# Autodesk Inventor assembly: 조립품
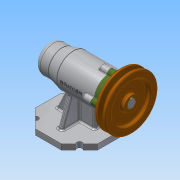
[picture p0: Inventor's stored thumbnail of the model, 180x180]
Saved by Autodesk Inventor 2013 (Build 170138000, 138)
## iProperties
Created: 2019-12
Part Number: 조립품
Document SubType Name: Assembly
Designer: Administrator
Author: Administrator
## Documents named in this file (12)
- C:\Users\Administrator\Desktop\491204V1027\조립품.iam
- C:\Users\Administrator\Desktop\491204V1027\본체.ipt
- C:\Users\Administrator\Desktop\491204V1027\축.ipt
- C:\Users\Administrator\Desktop\491204V1027\커버.ipt
- C:\Users\Administrator\Desktop\491204V1027\베어링 6004.ipt
- C:\Users\Administrator\Desktop\491204V1027\어댑터슬리브.ipt
- C:\Users\Administrator\Desktop\491204V1027\베어링 51202.ipt
- C:\Users\Administrator\Desktop\491204V1027\오일 실.ipt
- C:\Users\Administrator\Desktop\491204V1027\V벨트풀리.ipt
- C:\Users\Administrator\Desktop\491204V1027\키 5 x 5 x 16.ipt
- C:\Users\Administrator\Desktop\491204V1027\멈춤나사 M3.ipt
- C:\Users\Administrator\Desktop\491204V1027\볼트 M4.ipt
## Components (1 placed, 1 different names)
1. V벨트풀리:1 — 각도:2, 플러쉬:1, 각도:3
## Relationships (3: Angle 2, Flush 1)
- 각도:2 [Angle]: V벨트풀리:1
- 플러쉬:1 [Flush]: V벨트풀리:1
- 각도:3 [Angle]: V벨트풀리:1
